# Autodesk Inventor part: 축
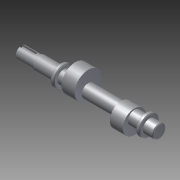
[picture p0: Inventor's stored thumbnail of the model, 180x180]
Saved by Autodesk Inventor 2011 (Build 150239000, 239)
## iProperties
Created: 2014-12
Part Number: 축
Document SubType Name: Modeling
Designer: user
Density: 1 g/cm^3
Author: user
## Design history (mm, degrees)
sketch "스케치1"
  geometry: L1 (-90, 0)-(90, 0); L2 (-90, 0)-(-90, 7.5); L3 (-90, 7.5)-(-66, 7.5); L4 (-66, 7.5)-(-66, 8.5); L5 (-66, 8.5)-(-39, 8.5); L6 (-39, 8.5)-(-39, 13); L7 (-39, 13)-(-34, 13); L8 (-34, 13)-(-34, 8.5); L9 (-34, 8.5)-(72, 8.5); L10 (72, 8.5)-(72, 13); L11 (72, 13)-(77, 13); L12 (77, 13)-(77, 8.5); L13 (77, 8.5)-(90, 8.5); L14 (90, 8.5)-(90, 0); 2 further points
  constraints: 28 end point, 7 parallel, 4 perpendicular, 2 point on line, 1 coincident, 1 horizontal, 1 midpoint, 1 vertical
  dimensions: "d0" = 180 distance of L1.start L1.end; "d1" = 15 diameter of L3 L1; "d2" = 17 diameter of L5 L1; "d3" = 17 diameter of L9 L1; "d4" = 26 diameter of L7 L1; "d5" = 5 distance of L10.end L11.end; "d6" = 26 diameter of L11 L1; "d7" = 24 distance of L2.end L3.end; "d8" = 27 distance of L4.end L5.end; "d9" = 5 distance of L6.end L7.end; "d10" = 13 distance of L12.end L13.end
revolve "회전1" sketch "스케치1" stored, may be unused: angle "d11" = 90 deg
node "작업 평면1"
sketch "스케치2"
  geometry: C1 r 8.5 at (0, 0) reference; C2 r 17.5 at (-6, 0); 1 further point
  constraints: 1 centre point, 1 horizontal alignment
  dimensions: "d13" = 35 diameter of C2; "d14" = 6 distance of C2.centre point (0, 0)
extrude "돌출1" join sketch "스케치2" distance "d15" = 17; taper "d16" = 0 deg
node "작업 평면2"
sketch "스케치3"
  geometry: C1 r 8.5 at (0, 0) reference; C2 r 8.5 at (0, 0) reference; C3 r 15 at (0, -5); 1 further point
  constraints: 1 centre point, 1 vertical alignment
  dimensions: "d18" = 30 diameter of C3; "d19" = 5 distance of C3.centre point (0, 0)
extrude "돌출2" join sketch "스케치3" distance "d20" = 17; taper "d21" = 0 deg
chamfer "모따기1" distance "d22" = 1; stored, may be unused: second distance "d23" = 2, angle "d24" = 45 deg
chamfer "모따기2" distance "d25" = 1; stored, may be unused: second distance "d26" = 2, angle "d27" = 45 deg
chamfer "모따기3" distance "d28" = 1; stored, may be unused: second distance "d29" = 2, angle "d30" = 45 deg
chamfer "모따기4" distance "d31" = 1; stored, may be unused: second distance "d32" = 2, angle "d33" = 45 deg
chamfer "모따기5" distance "d34" = 1; stored, may be unused: second distance "d35" = 2, angle "d36" = 45 deg
node "작업 평면3"
sketch "스케치4"
  geometry: L1 (58.5, 17.436)-(75.5, 17.436) reference; L2 (75.5, 17.436)-(75.5, 4) reference; L3 (75.5, 4)-(118.5, 4) reference; L4 (118.5, 4)-(118.5, 8.292) reference; L5 (118.5, 8.292)-(135.5, 8.292) reference; L6 (135.5, 8.292)-(135.5, 4) reference; L7 (135.5, 4)-(150, 4) reference; L8 (150, 4)-(150, 9.367) reference; L9 (151, 10.618)-(154, 10.618) reference; L10 (155, 9.367)-(155, 4) reference; L11 (155, 4)-(168, 4) reference; L12 (168, 4)-(168, -4) reference; L13 (168, -4)-(155, -4) reference; L14 (155, -4)-(155, -9.367) reference; L15 (154, -10.618)-(151, -10.618) reference; L16 (150, -9.367)-(150, -4) reference; L17 (150, -4)-(135.5, -4) reference; L18 (135.5, -4)-(135.5, -8.292) reference; L19 (135.5, -8.292)-(118.5, -8.292) reference; L20 (118.5, -8.292)-(118.5, -4) reference; L21 (118.5, -4)-(75.5, -4) reference; L22 (75.5, -4)-(75.5, -17.436) reference; L23 (75.5, -17.436)-(58.5, -17.436) reference; L24 (58.5, -17.436)-(58.5, -4) reference; L25 (58.5, -4)-(44, -4) reference; L26 (44, -4)-(44, -9.367) reference; L27 (43, -10.618)-(40, -10.618) reference; L28 (39, -9.367)-(39, -4) reference; L29 (39, -4)-(12, -4) reference; L30 (12, -4)-(12, 0) reference; L31 (12, 0)-(12, 4) reference; L32 (12, 4)-(39, 4) reference; L33 (39, 4)-(39, 9.367) reference; L34 (40, 10.618)-(43, 10.618) reference; L35 (44, 9.367)-(44, 4) reference; L36 (44, 4)-(58.5, 4) reference; L37 (58.5, 4)-(58.5, 17.436) reference; L38 (-11, 0)-(12, 0) reference; L39 (-12, -6.5)-(-12, 6.5) reference; L40 (5.5, 2.5)-(-12, 2.5); L41 (5.5, -2.5)-(-12, -2.5); A1 r 2.5 centre (5.5, 0) between (5.5, 2.5) and (5.5, -2.5); 1 further point
  constraints: 4 end point, 2 perpendicular, 2 point on circle, 2 point on line, 2 tangent, 1 centre point, 1 horizontal alignment, 8 other
  dimensions: "d37" = 20 dimension on A1 L39; "d38" = 5 diameter of A1
extrude "돌출3" cut sketch "스케치4" distance "d39" = 3; taper "d40" = 0 deg
chamfer "모따기6" distance "d41" = 1; stored, may be unused: second distance "d42" = 2, angle "d43" = 45 deg
node "솔리드1"
node "절단 모서리 투영1"
node "절단 모서리 투영2"
node "절단 모서리 투영3"
node "절단 모서리 투영4"
other parameters: "d12" = 14.5, "d17" = 14.5
